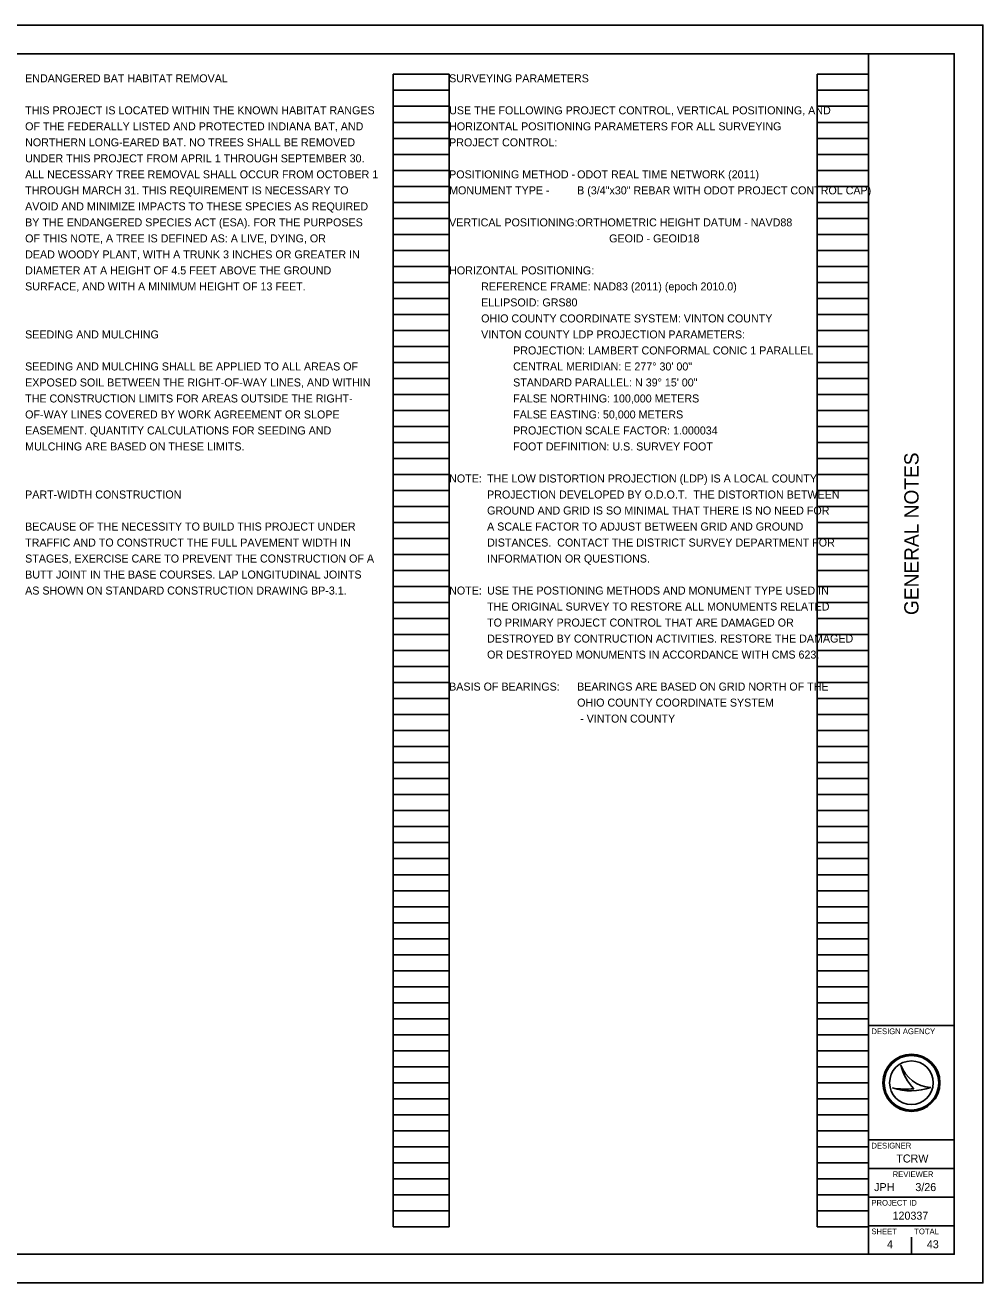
# Model space of a CAD drawing. Extents: x 0 to 34, y 0 to 22.
# Drawn here: x 17.24 to 34, y 0 to 22 of the extents above; entities that cross this region are included whole.
import ezdxf

# ---------------------------------------------------------------- set-up
doc = ezdxf.new("R2010")
doc.units = 0
for name, color, linetype in [('Default', 7, 'Continuous'), ('SH_Border', 7, 'Continuous'), ('SH_Cut_Line', 7, 'Continuous'), ('SH_Data', 7, 'Continuous'), ('SH_Text', 7, 'Continuous')]:
    doc.layers.add(name, color=color, linetype=linetype)

msp = doc.modelspace()

# ---------------------------------------------------------------- linework, layer by layer
at = {"layer": 'SH_Border'}
for p, q in [((32, 0.5), (32, 21.5)), ((32, 4.5), (33.5, 4.5)), ((32, 2.5), (33.5, 2.5)), ((32, 2), (33.5, 2)), ((32, 1.5), (33.5, 1.5)), ((32, 1), (33.5, 1))]:
    msp.add_line(p, q, dxfattribs=at)
msp.add_lwpolyline([(1.5, 21.5), (33.5, 21.5), (33.5, 0.5), (1.5, 0.5)], close=True, dxfattribs=at)
at = {"layer": 'SH_Cut_Line'}
msp.add_lwpolyline([(0, 0), (34, 0), (34, 22), (0, 22)], close=True, dxfattribs=at)
at = {"layer": 'SH_Data'}
for p, q in [((23.68, 0.98), (23.68, 21.14)), ((23.68, 21.14), (24.66, 21.14)), ((24.66, 0.98), (24.66, 21.14)), ((31.1, 0.98), (31.1, 21.14)), ((31.1, 21.14), (32, 21.14)), ((32, 0.98), (32, 21.14)), ((23.68, 20.86), (24.66, 20.86)), ((31.1, 20.86), (32, 20.86)), ((23.68, 20.58), (24.66, 20.58)), ((31.1, 20.58), (32, 20.58)), ((23.68, 20.3), (24.66, 20.3)), ((31.1, 20.3), (32, 20.3)), ((23.68, 20.02), (24.66, 20.02)), ((31.1, 20.02), (32, 20.02)), ((23.68, 19.74), (24.66, 19.74)), ((31.1, 19.74), (32, 19.74)), ((23.68, 19.46), (24.66, 19.46)), ((31.1, 19.46), (32, 19.46)), ((23.68, 19.18), (24.66, 19.18)), ((31.1, 19.18), (32, 19.18)), ((23.68, 18.9), (24.66, 18.9)), ((31.1, 18.9), (32, 18.9)), ((23.68, 18.62), (24.66, 18.62)), ((31.1, 18.62), (32, 18.62)), ((23.68, 18.34), (24.66, 18.34)), ((31.1, 18.34), (32, 18.34)), ((23.68, 18.06), (24.66, 18.06)), ((31.1, 18.06), (32, 18.06)), ((23.68, 17.78), (24.66, 17.78)), ((31.1, 17.78), (32, 17.78)), ((23.68, 17.5), (24.66, 17.5)), ((31.1, 17.5), (32, 17.5)), ((23.68, 17.22), (24.66, 17.22)), ((31.1, 17.22), (32, 17.22)), ((23.68, 16.94), (24.66, 16.94)), ((31.1, 16.94), (32, 16.94)), ((23.68, 16.66), (24.66, 16.66)), ((31.1, 16.66), (32, 16.66)), ((23.68, 16.38), (24.66, 16.38)), ((31.1, 16.38), (32, 16.38)), ((23.68, 16.1), (24.66, 16.1)), ((31.1, 16.1), (32, 16.1)), ((23.68, 15.82), (24.66, 15.82)), ((31.1, 15.82), (32, 15.82)), ((23.68, 15.54), (24.66, 15.54)), ((31.1, 15.54), (32, 15.54)), ((23.68, 15.26), (24.66, 15.26)), ((31.1, 15.26), (32, 15.26)), ((23.68, 14.98), (24.66, 14.98)), ((31.1, 14.98), (32, 14.98)), ((23.68, 14.7), (24.66, 14.7)), ((31.1, 14.7), (32, 14.7)), ((23.68, 14.42), (24.66, 14.42)), ((31.1, 14.42), (32, 14.42)), ((23.68, 14.14), (24.66, 14.14)), ((31.1, 14.14), (32, 14.14)), ((23.68, 13.86), (24.66, 13.86)), ((31.1, 13.86), (32, 13.86)), ((23.68, 13.58), (24.66, 13.58)), ((31.1, 13.58), (32, 13.58)), ((23.68, 13.3), (24.66, 13.3)), ((31.1, 13.3), (32, 13.3)), ((23.68, 13.02), (24.66, 13.02)), ((31.1, 13.02), (32, 13.02)), ((23.68, 12.74), (24.66, 12.74)), ((31.1, 12.74), (32, 12.74)), ((23.68, 12.46), (24.66, 12.46)), ((31.1, 12.46), (32, 12.46)), ((23.68, 12.18), (24.66, 12.18)), ((31.1, 12.18), (32, 12.18)), ((23.68, 11.9), (24.66, 11.9)), ((31.1, 11.9), (32, 11.9)), ((23.68, 11.62), (24.66, 11.62)), ((31.1, 11.62), (32, 11.62)), ((23.68, 11.34), (24.66, 11.34)), ((31.1, 11.34), (32, 11.34)), ((23.68, 11.06), (24.66, 11.06)), ((31.1, 11.06), (32, 11.06)), ((23.68, 10.78), (24.66, 10.78)), ((31.1, 10.78), (32, 10.78)), ((23.68, 10.5), (24.66, 10.5)), ((31.1, 10.5), (32, 10.5)), ((23.68, 10.22), (24.66, 10.22)), ((31.1, 10.22), (32, 10.22)), ((23.68, 9.94), (24.66, 9.94)), ((31.1, 9.94), (32, 9.94)), ((23.68, 9.66), (24.66, 9.66)), ((31.1, 9.66), (32, 9.66)), ((23.68, 9.38), (24.66, 9.38)), ((31.1, 9.38), (32, 9.38)), ((23.68, 9.1), (24.66, 9.1)), ((31.1, 9.1), (32, 9.1)), ((23.68, 8.82), (24.66, 8.82)), ((31.1, 8.82), (32, 8.82)), ((23.68, 8.54), (24.66, 8.54)), ((31.1, 8.54), (32, 8.54)), ((23.68, 8.26), (24.66, 8.26)), ((31.1, 8.26), (32, 8.26)), ((23.68, 7.98), (24.66, 7.98)), ((31.1, 7.98), (32, 7.98)), ((23.68, 7.7), (24.66, 7.7)), ((31.1, 7.7), (32, 7.7)), ((23.68, 7.42), (24.66, 7.42)), ((31.1, 7.42), (32, 7.42)), ((23.68, 7.14), (24.66, 7.14)), ((31.1, 7.14), (32, 7.14)), ((23.68, 6.86), (24.66, 6.86)), ((31.1, 6.86), (32, 6.86)), ((23.68, 6.58), (24.66, 6.58)), ((31.1, 6.58), (32, 6.58)), ((23.68, 6.3), (24.66, 6.3)), ((31.1, 6.3), (32, 6.3)), ((23.68, 6.02), (24.66, 6.02)), ((31.1, 6.02), (32, 6.02)), ((23.68, 5.74), (24.66, 5.74)), ((31.1, 5.74), (32, 5.74)), ((23.68, 5.46), (24.66, 5.46)), ((31.1, 5.46), (32, 5.46)), ((23.68, 5.18), (24.66, 5.18)), ((31.1, 5.18), (32, 5.18)), ((23.68, 4.9), (24.66, 4.9)), ((31.1, 4.9), (32, 4.9)), ((23.68, 4.62), (24.66, 4.62)), ((31.1, 4.62), (32, 4.62)), ((23.68, 4.34), (24.66, 4.34)), ((31.1, 4.34), (32, 4.34)), ((23.68, 4.06), (24.66, 4.06)), ((31.1, 4.06), (32, 4.06)), ((23.68, 3.78), (24.66, 3.78)), ((31.1, 3.78), (32, 3.78)), ((32.567, 3.81), (32.567, 3.81)), ((23.68, 3.5), (24.66, 3.5)), ((31.1, 3.5), (32, 3.5)), ((32.417, 3.41), (32.417, 3.41)), ((32.75, 3.5), (32.75, 3.5)), ((33.087, 3.419), (33.087, 3.419)), ((23.68, 3.22), (24.66, 3.22)), ((31.1, 3.22), (32, 3.22)), ((23.68, 2.94), (24.66, 2.94)), ((31.1, 2.94), (32, 2.94)), ((23.68, 2.66), (24.66, 2.66)), ((31.1, 2.66), (32, 2.66)), ((23.68, 2.38), (24.66, 2.38)), ((31.1, 2.38), (32, 2.38)), ((23.68, 2.1), (24.66, 2.1)), ((31.1, 2.1), (32, 2.1)), ((23.68, 1.82), (24.66, 1.82)), ((31.1, 1.82), (32, 1.82)), ((23.68, 1.54), (24.66, 1.54)), ((31.1, 1.54), (32, 1.54)), ((23.68, 1.26), (24.66, 1.26)), ((31.1, 1.26), (32, 1.26)), ((23.68, 0.98), (24.66, 0.98)), ((31.1, 0.98), (32, 0.98)), ((32.375, 0.675), (32.375, 0.675)), ((32.75, 0.5), (32.75, 0.8))]:
    msp.add_line(p, q, dxfattribs=at)
for radius in [0.5, 0.477, 0.477, 0.382]:
    msp.add_circle((32.75, 3.5), radius, dxfattribs=at)
for centre, radius, start, end in [((33.116, 3.998), 0.58, 198.9257, 198.9319), ((33.347, 3.97), 0.796, 191.6379, 191.6421), ((33.116, 3.998), 0.58, 198.9319, 267.1657), ((33.347, 3.97), 0.796, 191.6421, 226.0947), ((32.739, 4.37), 1.013, 251.4576, 290.0832), ((32.648, 4.654), 1.266, 259.4964, 259.4995), ((32.739, 4.37), 1.013, 251.4527, 251.4576), ((32.648, 4.654), 1.266, 259.4995, 276.6672)]:
    msp.add_arc(centre, radius, start, end, dxfattribs=at)

# ---------------------------------------------------------------- texts
at = {"layer": 'Default'}
for s, p in [('SURVEYING PARAMETERS', (24.66, 21)), ('USE THE FOLLOWING PROJECT CONTROL, VERTICAL POSITIONING, AND ', (24.66, 20.44)), ('HORIZONTAL POSITIONING PARAMETERS FOR ALL SURVEYING ', (24.66, 20.16)), ('PROJECT CONTROL:', (24.66, 19.88)), ('POSITIONING METHOD - ', (24.66, 19.32)), ('ODOT REAL TIME NETWORK (2011)', (26.9, 19.32)), ('MONUMENT TYPE - ', (24.66, 19.04)), ('B (3/4"x30" REBAR WITH ODOT PROJECT CONTROL CAP)', (26.9, 19.04)), ('VERTICAL POSITIONING:', (24.66, 18.48)), ('ORTHOMETRIC HEIGHT DATUM - NAVD88', (26.9, 18.48)), ('GEOID - GEOID18 ', (27.46, 18.2)), ('HORIZONTAL POSITIONING: ', (24.66, 17.64)), ('REFERENCE FRAME: NAD83 (2011) (epoch 2010.0)', (25.22, 17.36)), ('ELLIPSOID: GRS80', (25.22, 17.08)), ('OHIO COUNTY COORDINATE SYSTEM: VINTON COUNTY', (25.22, 16.8)), ('VINTON COUNTY LDP PROJECTION PARAMETERS:', (25.22, 16.52)), ('PROJECTION: LAMBERT CONFORMAL CONIC 1 PARALLEL', (25.78, 16.24)), ('CENTRAL MERIDIAN: E 277° 30\' 00"', (25.78, 15.96)), ('STANDARD PARALLEL: N 39° 15\' 00"', (25.78, 15.68)), ('FALSE NORTHING: 100,000 METERS', (25.78, 15.4)), ('FALSE EASTING: 50,000 METERS', (25.78, 15.12)), ('PROJECTION SCALE FACTOR: 1.000034', (25.78, 14.84)), ('FOOT DEFINITION: U.S. SURVEY FOOT', (25.78, 14.56)), ('NOTE:', (24.66, 14)), ('  THE LOW DISTORTION PROJECTION (LDP) IS A LOCAL COUNTY ', (25.22, 14)), ('  PROJECTION DEVELOPED BY O.D.O.T.  THE DISTORTION BETWEEN', (25.22, 13.72)), ('  GROUND AND GRID IS SO MINIMAL THAT THERE IS NO NEED FOR', (25.22, 13.44)), ('  A SCALE FACTOR TO ADJUST BETWEEN GRID AND GROUND ', (25.22, 13.16)), ('  DISTANCES.  CONTACT THE DISTRICT SURVEY DEPARTMENT FOR ', (25.22, 12.88)), ('  INFORMATION OR QUESTIONS.', (25.22, 12.6)), ('NOTE:', (24.66, 12.04)), ('  USE THE POSTIONING METHODS AND MONUMENT TYPE USED IN ', (25.22, 12.04)), ('  THE ORIGINAL SURVEY TO RESTORE ALL MONUMENTS RELATED ', (25.22, 11.76)), ('  TO PRIMARY PROJECT CONTROL THAT ARE DAMAGED OR ', (25.22, 11.48)), ('  DESTROYED BY CONTRUCTION ACTIVITIES. RESTORE THE DAMAGED ', (25.22, 11.2)), ('  OR DESTROYED MONUMENTS IN ACCORDANCE WITH CMS 623.', (25.22, 10.92)), ('BASIS OF BEARINGS:', (24.66, 10.36)), ('BEARINGS ARE BASED ON GRID NORTH OF THE', (26.9, 10.36)), ('OHIO COUNTY COORDINATE SYSTEM', (26.9, 10.08)), (' - VINTON COUNTY', (26.9, 9.8))]:
    msp.add_text(s, height=0.14, dxfattribs=at).set_placement(p)
at = {"layer": 'SH_Data'}
msp.add_text('GENERAL NOTES', height=0.25, rotation=90, dxfattribs=at).set_placement((32.875, 11.682))
for s, height, p in [('DESIGN AGENCY', 0.1, (32.05, 4.35)), ('DESIGNER', 0.1, (32.05, 2.35)), ('TCRW', 0.14, (32.486, 2.105)), ('REVIEWER', 0.1, (32.422, 1.85)), ('JPH', 0.14, (32.098, 1.605)), ('3/26', 0.14, (32.819, 1.605)), ('PROJECT ID', 0.1, (32.05, 1.35)), ('120337', 0.14, (32.42, 1.105)), ('SHEET', 0.1, (32.05, 0.85)), ('TOTAL', 0.1, (32.8, 0.85)), ('4', 0.14, (32.322, 0.605)), ('43', 0.14, (33.02, 0.605))]:
    msp.add_text(s, height=height, dxfattribs=at).set_placement(p)
at = {"layer": 'SH_Text'}
for s, p in [('ENDANGERED BAT HABITAT REMOVAL', (17.24, 21)), ('THIS PROJECT IS LOCATED WITHIN THE KNOWN HABITAT RANGES', (17.24, 20.44)), ('OF THE FEDERALLY LISTED AND PROTECTED INDIANA BAT, AND', (17.24, 20.16)), ('NORTHERN LONG-EARED BAT. NO TREES SHALL BE REMOVED', (17.24, 19.88)), ('UNDER THIS PROJECT FROM APRIL 1 THROUGH SEPTEMBER 30.', (17.24, 19.6)), ('ALL NECESSARY TREE REMOVAL SHALL OCCUR FROM OCTOBER 1', (17.24, 19.32)), ('THROUGH MARCH 31. THIS REQUIREMENT IS NECESSARY TO', (17.24, 19.04)), ('AVOID AND MINIMIZE IMPACTS TO THESE SPECIES AS REQUIRED', (17.24, 18.76)), ('BY THE ENDANGERED SPECIES ACT (ESA). FOR THE PURPOSES', (17.24, 18.48)), ('OF THIS NOTE, A TREE IS DEFINED AS: A LIVE, DYING, OR', (17.24, 18.2)), ('DEAD WOODY PLANT, WITH A TRUNK 3 INCHES OR GREATER IN', (17.24, 17.92)), ('DIAMETER AT A HEIGHT OF 4.5 FEET ABOVE THE GROUND', (17.24, 17.64)), ('SURFACE, AND WITH A MINIMUM HEIGHT OF 13 FEET.', (17.24, 17.36)), ('SEEDING AND MULCHING', (17.24, 16.52)), ('SEEDING AND MULCHING SHALL BE APPLIED TO ALL AREAS OF', (17.24, 15.96)), ('EXPOSED SOIL BETWEEN THE RIGHT-OF-WAY LINES, AND WITHIN', (17.24, 15.68)), ('THE CONSTRUCTION LIMITS FOR AREAS OUTSIDE THE RIGHT-', (17.24, 15.4)), ('OF-WAY LINES COVERED BY WORK AGREEMENT OR SLOPE', (17.24, 15.12)), ('EASEMENT. QUANTITY CALCULATIONS FOR SEEDING AND', (17.24, 14.84)), ('MULCHING ARE BASED ON THESE LIMITS.', (17.24, 14.56)), ('PART-WIDTH CONSTRUCTION', (17.24, 13.72)), ('BECAUSE OF THE NECESSITY TO BUILD THIS PROJECT UNDER', (17.24, 13.16)), ('TRAFFIC AND TO CONSTRUCT THE FULL PAVEMENT WIDTH IN', (17.24, 12.88)), ('STAGES, EXERCISE CARE TO PREVENT THE CONSTRUCTION OF A', (17.24, 12.6)), ('BUTT JOINT IN THE BASE COURSES. LAP LONGITUDINAL JOINTS', (17.24, 12.32)), ('AS SHOWN ON STANDARD CONSTRUCTION DRAWING BP-3.1.', (17.24, 12.04))]:
    msp.add_text(s, height=0.14, dxfattribs=at).set_placement(p)

doc.saveas('drawing.dxf')
